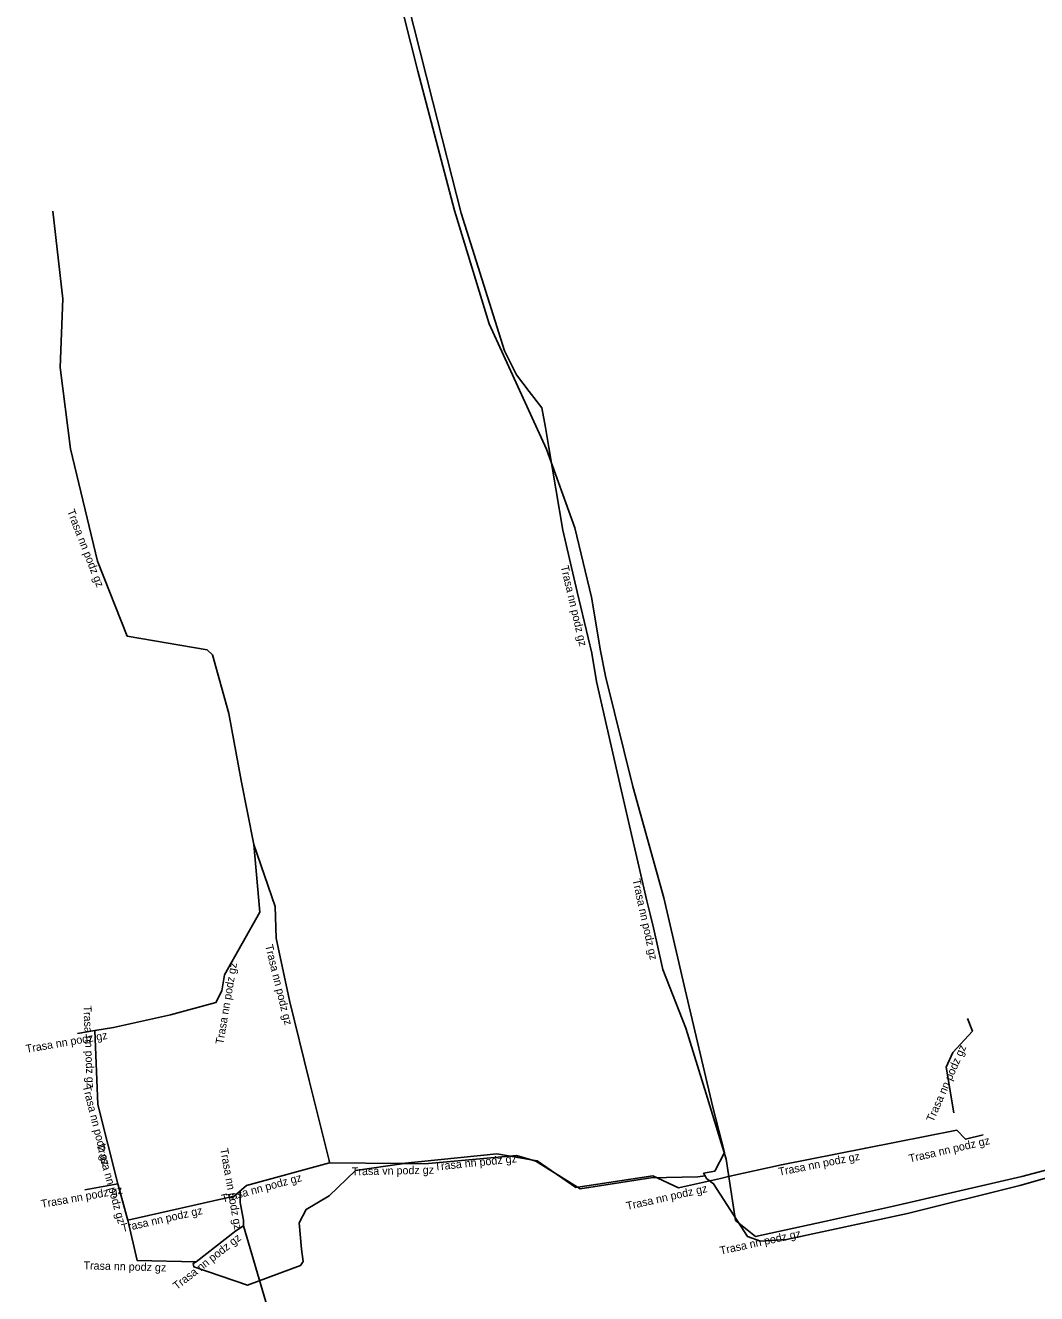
# Model space of a CAD drawing. Extents: x -473162 to -472629, y -1107202 to -1106680.
# Drawn here: x -472853.7 to -472790.5, y -1106838.5 to -1106759.3 of the extents above; entities that cross this region are included whole.
import ezdxf

# ---------------------------------------------------------------- set-up
doc = ezdxf.new("R2010")
doc.units = 0
for name, color, linetype in [('Popiskový text - Ostatní atributy Trasy', 7, 'Continuous'), ('Spojnice NN', 7, 'Continuous'), ('Spojnice VN', 7, 'Continuous')]:
    doc.layers.add(name, color=color, linetype=linetype)

msp = doc.modelspace()

# ---------------------------------------------------------------- linework, layer by layer
at = {"layer": 'Spojnice NN'}
for points in [[(-472823.755, -1106779.595), (-472826.46, -1106771.01), (-472828.235, -1106764.045), (-472831.015, -1106753.02), (-472832.515, -1106746.745), (-472834.015, -1106740.47), (-472836.34, -1106730.705), (-472838.522, -1106721.662), (-472840.705, -1106712.62), (-472842.02, -1106706.825), (-472843.335, -1106701.03), (-472844.94, -1106695.15), (-472846.24, -1106690.01), (-472846.07, -1106687.715), (-472845.803, -1106687.048)], [(-472851.97, -1106770.87), (-472851.335, -1106776.365), (-472851.515, -1106780.645), (-472850.865, -1106785.73), (-472849.17, -1106792.74), (-472847.335, -1106797.425), (-472842.325, -1106798.285), (-472841.995, -1106798.585), (-472840.975, -1106802.26), (-472840.2, -1106806.445), (-472839.405, -1106810.448)], [(-472814.755, -1106814.375), (-472814.86, -1106813.965), (-472816.44, -1106807.11), (-472818.02, -1106800.255), (-472818.305, -1106798.5), (-472819.21, -1106794.655), (-472820.115, -1106790.81), (-472820.548, -1106788.222), (-472820.98, -1106785.635), (-472821.198, -1106784.402), (-472821.415, -1106783.17), (-472822.21, -1106782.14), (-472823.005, -1106781.11), (-472823.755, -1106779.595)], [(-472839.405, -1106810.448), (-472839.035, -1106814.665), (-472840.138, -1106816.63), (-472841.24, -1106818.595), (-472841.408, -1106819.58), (-472841.785, -1106820.305), (-472844.615, -1106821.075), (-472848.19, -1106821.87), (-472849.345, -1106822.069)], [(-472834.69, -1106830.325), (-472834.71, -1106830.195), (-472835.952, -1106825.192), (-472837.195, -1106820.19), (-472838.025, -1106816.295), (-472838.085, -1106814.315), (-472839.405, -1106810.448)], [(-472813.87, -1106818.255), (-472814.445, -1106815.64), (-472814.652, -1106814.802), (-472814.755, -1106814.375)], [(-472787.6, -1106830.16), (-472791.435, -1106831.185), (-472799.465, -1106833.045), (-472803.772, -1106833.988), (-472808.08, -1106834.93), (-472809.32, -1106833.93), (-472809.9, -1106830.105), (-472811.162, -1106826.015), (-472812.425, -1106821.925), (-472813.87, -1106818.255)], [(-472795.69, -1106827.2), (-472796.16, -1106824.35), (-472795.76, -1106823.44), (-472794.525, -1106822.105), (-472794.843, -1106821.31)], [(-472849.345, -1106822.069), (-472850.43, -1106822.255)], [(-472849.345, -1106822.069), (-472849.155, -1106826.68)], [(-472849.155, -1106826.68), (-472847.911, -1106831.643)], [(-472795.512, -1106828.293), (-472801.192, -1106829.412), (-472806.455, -1106830.45), (-472809.672, -1106831.172), (-472810.261, -1106831.304)], [(-472795.512, -1106828.293), (-472794.96, -1106828.845), (-472793.855, -1106828.59)], [(-472814.485, -1106831.15), (-472819.305, -1106831.87), (-472821.725, -1106830.205), (-472824.24, -1106829.77), (-472830.16, -1106830.375), (-472834.69, -1106830.325)], [(-472834.69, -1106830.325), (-472839.875, -1106831.745), (-472840.645, -1106832.42)], [(-472847.911, -1106831.643), (-472849.977, -1106832.012)], [(-472847.911, -1106831.643), (-472847.365, -1106833.62), (-472847.286, -1106833.921)], [(-472810.261, -1106831.304), (-472812.89, -1106831.895), (-472814.485, -1106831.15)], [(-472847.286, -1106833.921), (-472840.645, -1106832.42)], [(-472840.26, -1106832.082), (-472840.265, -1106832.81), (-472840.07, -1106833.912), (-472840.065, -1106834.27)], [(-472843.024, -1106836.522), (-472846.702, -1106836.422), (-472847.286, -1106833.921)], [(-472840.065, -1106834.27), (-472838.552, -1106839.368), (-472837.035, -1106844.14), (-472834.705, -1106849.515), (-472832.6, -1106854.195), (-472830.24, -1106860.785), (-472828.94, -1106864.51), (-472828.63, -1106865.75), (-472828.43, -1106866.84), (-472827.775, -1106869.815), (-472826.385, -1106876.755), (-472826.975, -1106878.22), (-472834.058, -1106879.93), (-472841.19, -1106882.14), (-472843.64, -1106882.58), (-472846.095, -1106882.795), (-472848.005, -1106883.66), (-472848.875, -1106884.86), (-472846.97, -1106892.43)], [(-472840.065, -1106834.27), (-472840.545, -1106834.578), (-472843.024, -1106836.522)]]:
    msp.add_lwpolyline(points, dxfattribs=at)
at = {"layer": 'Spojnice VN'}
for points in [[(-472811.23, -1106831.145), (-472811.32, -1106830.98), (-472810.62, -1106830.86), (-472810.02, -1106829.69), (-472810.75, -1106826.86), (-472812.48, -1106819.52), (-472813.8, -1106813.78), (-472815.73, -1106806.83), (-472817.45, -1106799.93), (-472817.76, -1106798.34), (-472818.33, -1106795), (-472819.37, -1106790.66), (-472821.13, -1106785.74), (-472824.71, -1106777.92), (-472826.88, -1106770.83), (-472829.18, -1106762.14), (-472832.27, -1106749.84)], [(-472740.7, -1106823.52), (-472748.12, -1106825.04), (-472750.28, -1106823.4), (-472750.91, -1106822.13), (-472760.13, -1106824.56), (-472763.33, -1106825.27), (-472769.09, -1106826.53), (-472787.12, -1106830.48), (-472791.57, -1106831.75), (-472798.59, -1106833.5), (-472806.15, -1106835.11), (-472807.76, -1106835.22), (-472808.57, -1106834.94), (-472810.7, -1106831.64), (-472811.14, -1106831.31), (-472811.23, -1106831.145)], [(-472811.23, -1106831.145), (-472811.69, -1106831.21), (-472814.61, -1106831.27), (-472819.04, -1106831.95), (-472821.805, -1106830.235), (-472823, -1106829.875), (-472823.915, -1106829.95), (-472828.495, -1106830.365), (-472830.16, -1106830.4), (-472833.055, -1106830.8), (-472834.715, -1106832.385), (-472836.155, -1106833.24), (-472836.575, -1106834.07), (-472836.43, -1106835.72), (-472836.34, -1106836.5), (-472836.49, -1106836.735), (-472839.82, -1106837.97), (-472843.156, -1106836.828), (-472843.202, -1106836.613), (-472843.024, -1106836.522)]]:
    msp.add_lwpolyline(points, dxfattribs=at)

# ---------------------------------------------------------------- texts
at = {"layer": 'Popiskový text - Ostatní atributy Trasy'}
for s, rotation, p in [('Trasa nn podz gz', 291.38906, (-472851.094, -1106789.612)), ('Trasa nn podz gz', 283.24467, (-472820.25, -1106793.071)), ('Trasa nn podz gz', 282.40115, (-472815.768, -1106812.648)), ('Trasa nn podz gz', 283.95536, (-472838.718, -1106816.758)), ('Trasa nn podz gz', 80.32086, (-472841.325, -1106822.958)), ('Trasa nn podz gz', 272.35958, (-472850.06, -1106820.511)), ('Trasa nn podz gz', 9.72758, (-472853.615, -1106823.46)), ('Trasa nn podz gz', 66.27161, (-472796.975, -1106827.819)), ('Trasa nn podz gz', 284.07155, (-472850.11, -1106825.543)), ('Trasa nn podz gz', 285.43888, (-472849.26, -1106829.201)), ('Trasa nn podz gz', 12.99462, (-472798.436, -1106830.314)), ('Trasa nn podz gz', 280.03467, (-472841.519, -1106829.458)), ('Trasa nn podz gz', 5.83514, (-472828.106, -1106830.819)), ('Trasa nn podz gz', 11.15702, (-472806.592, -1106831.14)), ('Trasa vn podz gz', 1.20424, (-472833.284, -1106831.116)), ('Trasa nn podz gz', 15.31588, (-472841.36, -1106832.826)), ('Trasa nn podz gz', 10.11987, (-472852.663, -1106833.151)), ('Trasa nn podz gz', 12.66314, (-472816.09, -1106833.28)), ('Trasa nn podz gz', 12.73601, (-472847.62, -1106834.663)), ('Trasa nn podz gz', 38.1054, (-472844.223, -1106838.289)), ('Trasa nn podz gz', 12.33433, (-472810.248, -1106836.069)), ('Trasa nn podz gz', 358.44627, (-472850.057, -1106836.981))]:
    msp.add_text(s, height=0.5, rotation=rotation, dxfattribs=at).set_placement(p)

doc.saveas('drawing.dxf')
